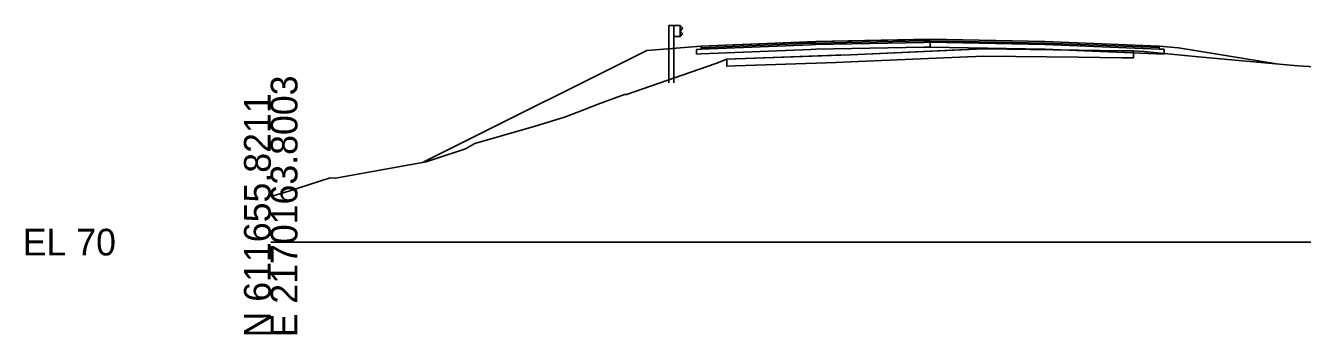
# Model space of a CAD drawing. Extents: x -26 to 1303, y -3010 to 12023.
# Drawn here: x 974.3 to 1108.1, y 2490.3 to 2522.7 of the extents above; entities that cross this region are included whole.
import ezdxf

# ---------------------------------------------------------------- set-up
doc = ezdxf.new("R2010")
doc.units = 0
for name, color, linetype in [('RD_GPK_XS_Cell', 7, 'Continuous'), ('RD_PD_Final_TrvlWay', 7, 'Continuous'), ('RD_XS_Base', 7, 'Continuous'), ('RD_XS_ExGround', 7, 'Continuous'), ('RD_XS_ExPaveRet', 7, 'Continuous'), ('RD_XS_GR', 7, 'Continuous'), ('RD_XS_Greenside', 7, 'Continuous'), ('RD_XS_Pave', 7, 'Continuous'), ('RD_XS_PaveOvlay_CP', 7, 'Continuous'), ('RD_XS_TieSlope', 7, 'Continuous')]:
    doc.layers.add(name, color=color, linetype=linetype)

msp = doc.modelspace()

# ---------------------------------------------------------------- linework, layer by layer
at = {"layer": 'RD_GPK_XS_Cell'}
msp.add_line((1000, 2500), (1150, 2500), dxfattribs=at)
at = {"layer": 'RD_PD_Final_TrvlWay'}
msp.add_lwpolyline([(1042.23, 2516.73), (1042.23, 2520.33), (1041.73, 2520.29), (1041.73, 2516.73)], dxfattribs=at)
at = {"layer": 'RD_XS_Base'}
for p, q in [((1069.11, 2521.12), (1069.11, 2521.13)), ((1069.11, 2521.13), (1069.11, 2521.09)), ((1069.11, 2520.97), (1069.11, 2521.13)), ((1069.11, 2521.13), (1069.11, 2521.13)), ((1069.11, 2521.13), (1069.11, 2521.13)), ((1069.11, 2521.13), (1069.11, 2520.47)), ((1069.11, 2520.97), (1069.11, 2521.12)), ((1069.11, 2521.09), (1069.11, 2520.47)), ((1045.09, 2520.24), (1044.61, 2520.22)), ((1044.61, 2520.22), (1044.61, 2520.21)), ((1044.61, 2520.21), (1044.61, 2519.72)), ((1044.61, 2519.72), (1045.09, 2519.74)), ((1045.11, 2520.24), (1045.09, 2520.24)), ((1045.09, 2519.74), (1045.11, 2519.74)), ((1056.6, 2520.71), (1045.11, 2520.24)), ((1045.11, 2519.74), (1056.6, 2520.21)), ((1057.11, 2520.73), (1056.6, 2520.71)), ((1056.6, 2520.21), (1057.11, 2520.23)), ((1068.45, 2520.95), (1057.11, 2520.73)), ((1057.11, 2520.23), (1068.45, 2520.45)), ((1069.11, 2520.97), (1068.45, 2520.95)), ((1068.45, 2520.45), (1069.11, 2520.47)), ((1069.11, 2520.94), (1069.11, 2520.97)), ((1069.11, 2520.47), (1069.11, 2520.97)), ((1069.11, 2520.97), (1069.11, 2520.97)), ((1069.11, 2520.97), (1069.11, 2520.97)), ((1069.11, 2520.97), (1069.11, 2520.97)), ((1081.11, 2520.73), (1069.11, 2520.97)), ((1069.11, 2520.47), (1069.11, 2520.94)), ((1069.11, 2520.47), (1069.11, 2520.47)), ((1069.11, 2520.47), (1069.11, 2520.47)), ((1069.11, 2520.47), (1081.11, 2520.23)), ((1093.11, 2520.25), (1081.11, 2520.73)), ((1081.11, 2520.23), (1093.61, 2519.73)), ((1083.11, 2520.65), (1083.11, 2520.65)), ((1083.11, 2520.15), (1083.11, 2520.15)), ((1093.61, 2520.23), (1093.11, 2520.25)), ((1093.11, 2520.25), (1093.11, 2520.25)), ((1093.61, 2519.73), (1093.61, 2520.23)), ((1093.61, 2520.23), (1093.61, 2520.23))]:
    msp.add_line(p, q, dxfattribs=at)
at = {"layer": 'RD_XS_ExGround'}
msp.add_lwpolyline([(1000, 2504.79), (1001.89, 2505.35), (1006.23, 2506.75), (1006.8, 2506.7), (1016.28, 2508.42), (1017.23, 2508.73), (1020.42, 2509.8), (1021.4, 2510.35), (1027.72, 2512.16), (1030.77, 2513.1), (1032.27, 2513.66), (1034.32, 2514.47), (1036.04, 2515.12), (1037.09, 2515.49), (1037.27, 2515.49), (1046.65, 2518.75), (1047.79, 2519.2), (1049.74, 2519.28), (1060.77, 2519.66), (1074.72, 2520.27), (1089.21, 2520.08), (1090.4, 2520.07), (1091.5, 2519.99), (1097.21, 2519.44), (1107.63, 2518.49), (1116.58, 2517.97)], dxfattribs=at)
at = {"layer": 'RD_XS_ExPaveRet'}
for points in [[(1090.4, 2520.07), (1090.4, 2520.07), (1089.21, 2520.08), (1084.64, 2520.14), (1074.72, 2520.27), (1072.18, 2520.16), (1060.77, 2519.66), (1059.26, 2519.61), (1049.74, 2519.28), (1048.68, 2519.23), (1047.79, 2519.2), (1047.79, 2519.1), (1047.79, 2518.45), (1048.68, 2518.48), (1049.74, 2518.53), (1059.26, 2518.86), (1060.77, 2518.91), (1072.18, 2519.41), (1074.72, 2519.52), (1084.64, 2519.39), (1089.21, 2519.33), (1090.4, 2519.32), (1090.4, 2519.32), (1090.4, 2519.32), (1090.4, 2519.32), (1090.4, 2519.55), (1090.4, 2520.07), (1090.4, 2520.07), (1090.4, 2520.07)], [(1090.4, 2520.07), (1090.4, 2520.07), (1089.21, 2520.08), (1084.64, 2520.14), (1074.72, 2520.27), (1072.18, 2520.16), (1060.77, 2519.66), (1059.26, 2519.61), (1049.74, 2519.28), (1048.68, 2519.23), (1047.79, 2519.2), (1047.79, 2519.1), (1047.79, 2518.45), (1048.68, 2518.48), (1049.74, 2518.53), (1059.26, 2518.86), (1060.77, 2518.91), (1072.18, 2519.41), (1074.72, 2519.52), (1084.64, 2519.39), (1089.21, 2519.33), (1090.4, 2519.32), (1090.4, 2519.32), (1090.4, 2519.32), (1090.4, 2519.55), (1090.4, 2520.07), (1090.4, 2520.07)]]:
    msp.add_lwpolyline(points, dxfattribs=at)
at = {"layer": 'RD_XS_GR'}
for p, q in [((1041.73, 2520.29), (1041.73, 2522.73)), ((1041.73, 2522.73), (1041.98, 2522.73)), ((1041.98, 2522.73), (1042.23, 2522.73)), ((1042.23, 2522.73), (1042.23, 2520.33)), ((1042.23, 2521.56), (1042.23, 2522.73)), ((1042.23, 2522.73), (1042.9, 2522.73)), ((1042.9, 2522.73), (1042.9, 2521.56)), ((1042.91, 2522.72), (1042.9, 2522.73)), ((1042.9, 2522.73), (1042.9, 2522.7)), ((1042.9, 2522.7), (1042.9, 2521.56)), ((1042.9, 2522.14), (1043.16, 2522.43)), ((1043.17, 2522.44), (1042.91, 2522.72)), ((1043.16, 2522.43), (1043.17, 2522.44)), ((1042.9, 2521.56), (1042.23, 2521.56)), ((1042.91, 2522.14), (1042.9, 2522.14)), ((1042.9, 2521.56), (1043.16, 2521.84)), ((1043.17, 2521.85), (1042.91, 2522.14)), ((1043.16, 2521.84), (1043.17, 2521.85)), ((1042.23, 2520.33), (1041.73, 2520.29))]:
    msp.add_line(p, q, dxfattribs=at)
at = {"layer": 'RD_XS_Greenside'}
for p, q in [((1018.5, 2509.65), (1039.42, 2520.11)), ((1095.11, 2520.4), (1105.38, 2518.69)), ((1015.92, 2508.36), (1018.5, 2509.65))]:
    msp.add_line(p, q, dxfattribs=at)
at = {"layer": 'RD_XS_Pave'}
for p, q in [((1056.6, 2521.02), (1045.11, 2520.56)), ((1057.11, 2521.04), (1056.6, 2521.02)), ((1068.45, 2521.27), (1057.11, 2521.04)), ((1068.45, 2521.11), (1057.11, 2520.88)), ((1057.11, 2520.88), (1068.45, 2521.11)), ((1069.11, 2521.28), (1068.45, 2521.27)), ((1069.11, 2521.13), (1068.45, 2521.11)), ((1068.45, 2521.11), (1069.11, 2521.13)), ((1081.11, 2521.04), (1069.11, 2521.28)), ((1069.11, 2521.28), (1069.11, 2521.28)), ((1069.11, 2521.28), (1069.11, 2521.28)), ((1069.11, 2521.12), (1069.11, 2521.13)), ((1069.11, 2521.13), (1069.11, 2521.12)), ((1069.11, 2520.97), (1069.11, 2521.13)), ((1069.11, 2521.13), (1069.11, 2521.13)), ((1069.11, 2521.13), (1069.11, 2521.13)), ((1069.11, 2521.13), (1069.11, 2521.13)), ((1069.11, 2521.13), (1069.11, 2521.13)), ((1069.11, 2521.13), (1081.11, 2520.89)), ((1081.11, 2520.89), (1069.11, 2521.13)), ((1069.11, 2521.13), (1069.11, 2521.13)), ((1069.11, 2521.13), (1069.11, 2521.13)), ((1069.11, 2521.13), (1069.11, 2520.97)), ((1069.11, 2520.97), (1069.11, 2521.12)), ((1069.11, 2521.12), (1069.11, 2520.97)), ((1093.11, 2520.56), (1081.11, 2521.04)), ((1056.6, 2520.86), (1045.11, 2520.4)), ((1045.11, 2520.4), (1056.6, 2520.86)), ((1045.11, 2520.24), (1056.6, 2520.71)), ((1045.11, 2520.56), (1045.11, 2520.56)), ((1045.11, 2520.56), (1045.11, 2520.4)), ((1045.11, 2520.4), (1045.11, 2520.4)), ((1045.11, 2520.4), (1045.11, 2520.24)), ((1057.11, 2520.88), (1056.6, 2520.86)), ((1056.6, 2520.86), (1057.11, 2520.88)), ((1056.6, 2520.71), (1057.11, 2520.73)), ((1057.11, 2520.73), (1068.45, 2520.95)), ((1068.45, 2520.95), (1069.11, 2520.97)), ((1069.11, 2520.97), (1069.11, 2520.97)), ((1069.11, 2520.97), (1069.11, 2520.97)), ((1069.11, 2520.97), (1081.11, 2520.73)), ((1081.11, 2520.89), (1093.11, 2520.41)), ((1093.11, 2520.41), (1081.11, 2520.89)), ((1081.11, 2520.73), (1093.11, 2520.25)), ((1083.11, 2520.96), (1083.11, 2520.96)), ((1083.11, 2520.81), (1083.11, 2520.81)), ((1083.11, 2520.81), (1083.11, 2520.81)), ((1083.11, 2520.65), (1083.11, 2520.65)), ((1093.11, 2520.41), (1093.11, 2520.56)), ((1093.11, 2520.56), (1093.11, 2520.56)), ((1093.11, 2520.25), (1093.11, 2520.41)), ((1093.11, 2520.41), (1093.11, 2520.41))]:
    msp.add_line(p, q, dxfattribs=at)
at = {"layer": 'RD_XS_PaveOvlay_CP'}
for p, q in [((1045.11, 2520.56), (1057.11, 2521.04)), ((1057.11, 2521.04), (1069.11, 2521.28)), ((1069.11, 2521.28), (1081.11, 2521.04)), ((1081.11, 2521.04), (1093.11, 2520.56))]:
    msp.add_line(p, q, dxfattribs=at)
at = {"layer": 'RD_XS_TieSlope'}
for p, q in [((1045.11, 2520.56), (1039.42, 2520.11)), ((1093.11, 2520.56), (1095.11, 2520.4))]:
    msp.add_line(p, q, dxfattribs=at)

# ---------------------------------------------------------------- texts
at = {"layer": 'RD_GPK_XS_Cell'}
for s, p in [('E 2170163.8003', (1002.8, 2490)), ('N 611655.8211', (1000, 2490))]:
    msp.add_text(s, height=2.8, rotation=90, dxfattribs=at).set_placement(p)
msp.add_text('EL 70', height=2.8, dxfattribs=at).set_placement((974, 2498.6))

doc.saveas('drawing.dxf')
